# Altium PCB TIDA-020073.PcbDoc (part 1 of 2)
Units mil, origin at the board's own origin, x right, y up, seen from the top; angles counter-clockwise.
Board outline 2125.98 x 2598.43 mil, 4 copper layers (Top Copper, Signal Layer 1, Signal Layer 2, Bottom Copper), stack 62.45 mil thick; 144 components, 83 nets, 376 pads, 155 vias.
Unrouted connection lines stored in the file: 1.
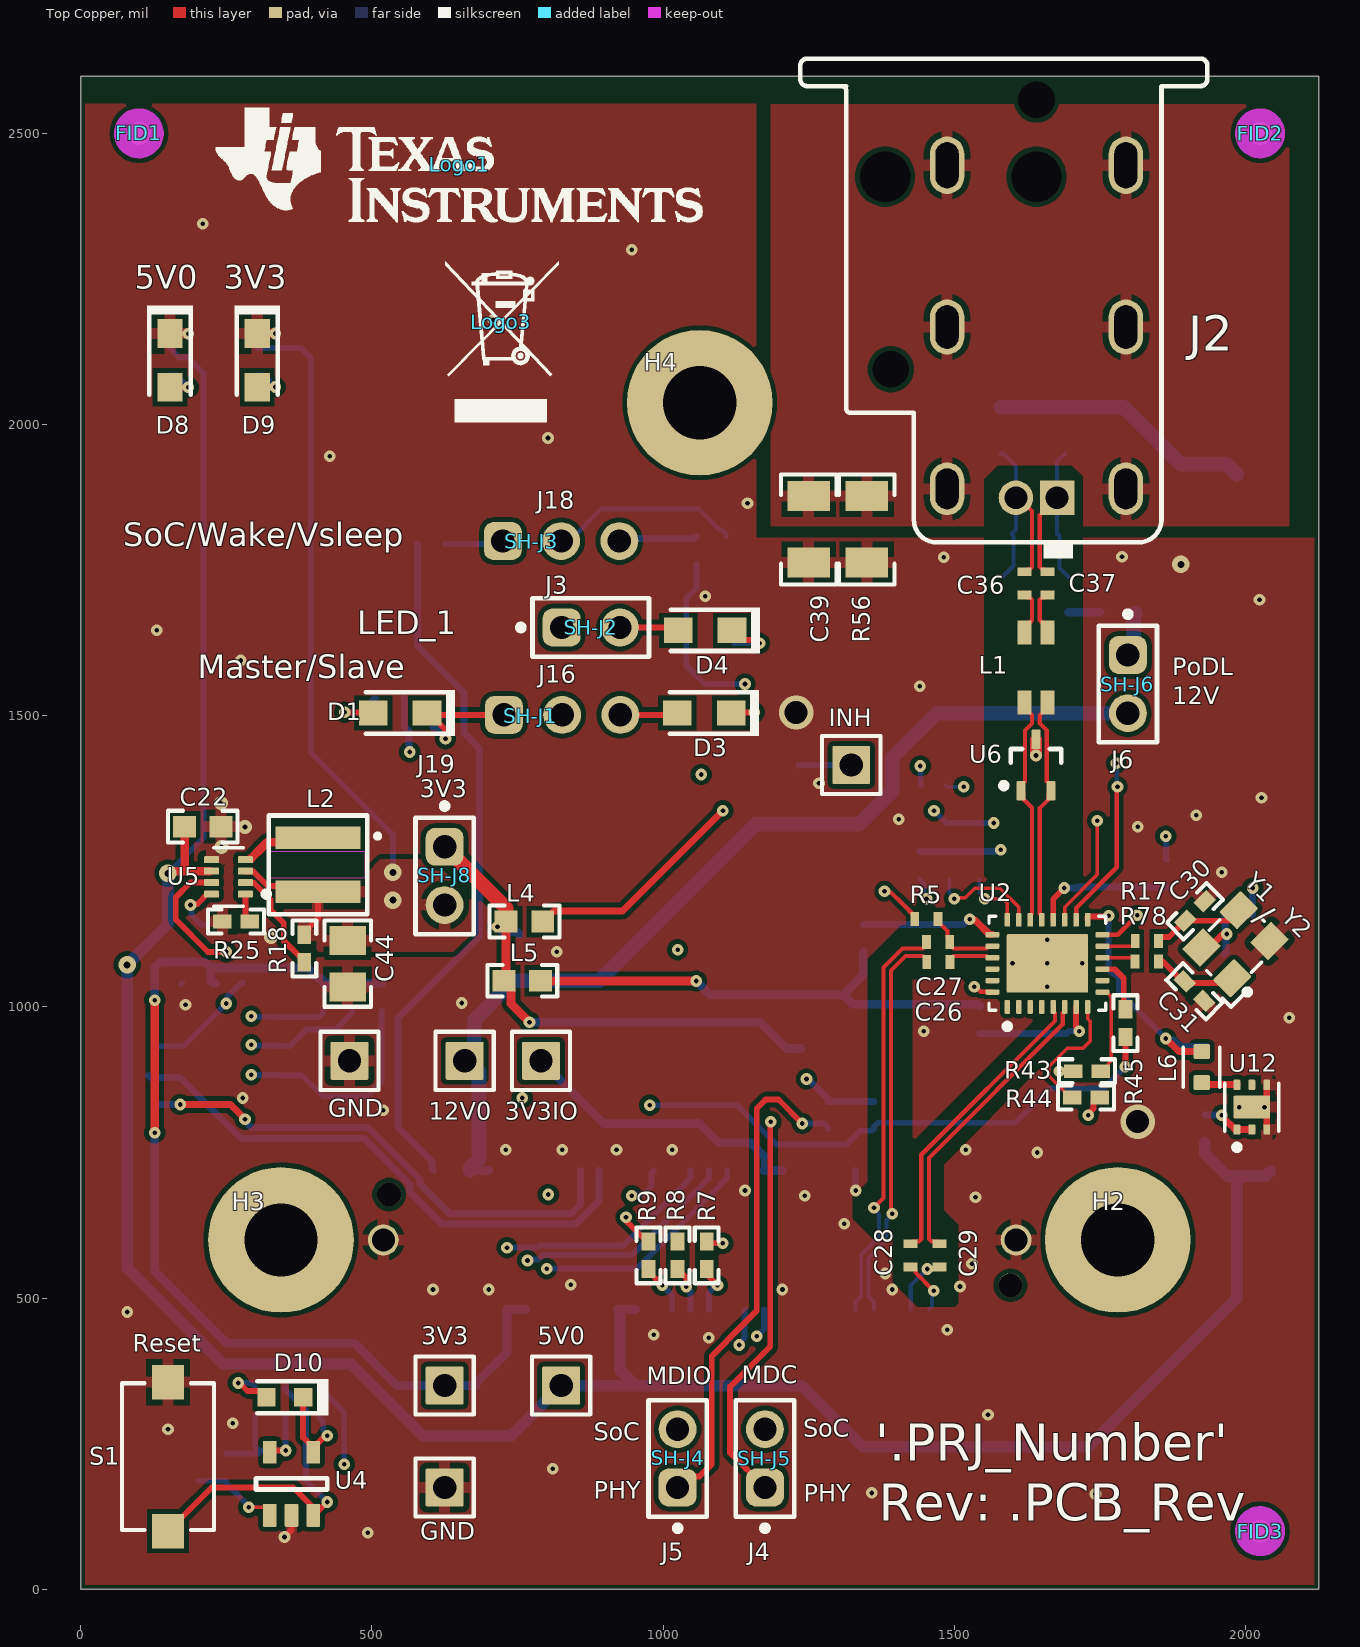
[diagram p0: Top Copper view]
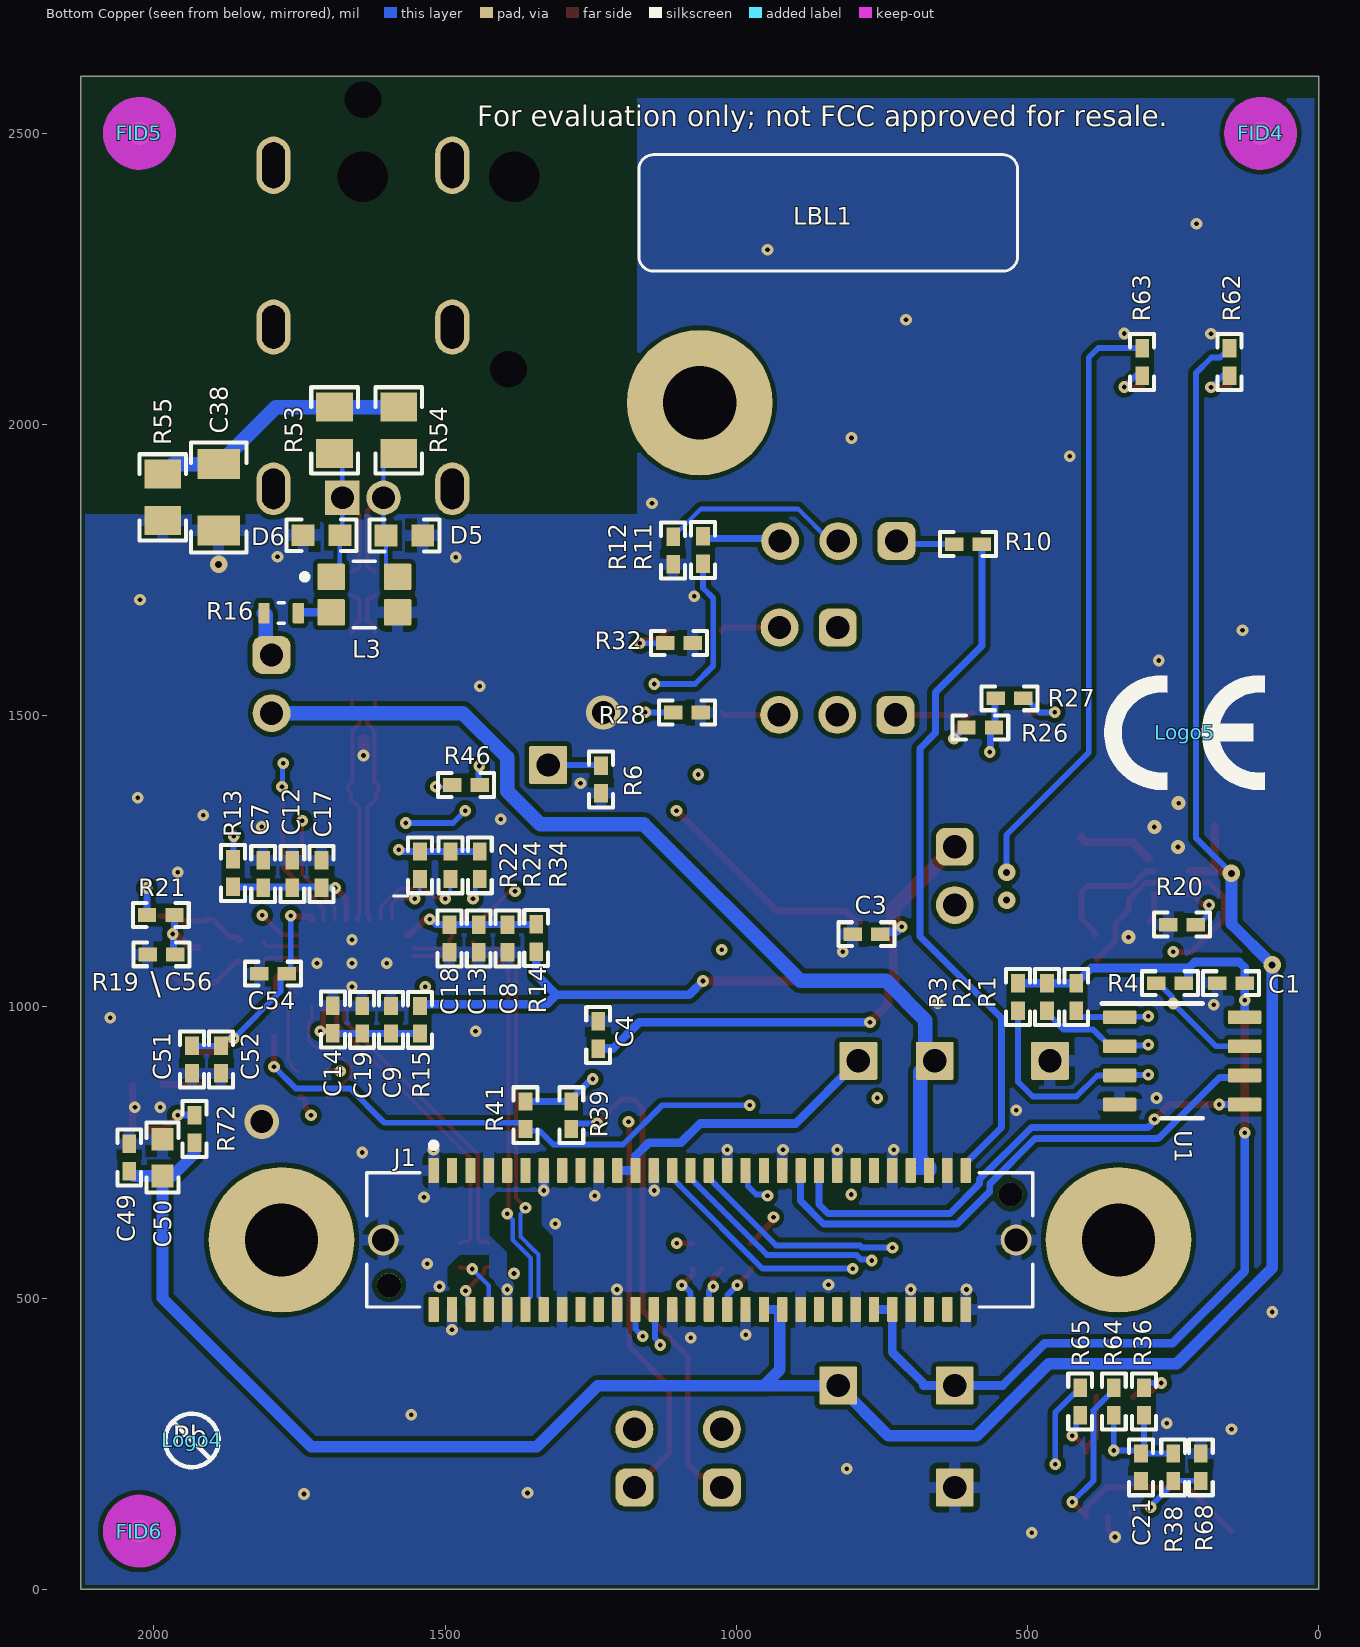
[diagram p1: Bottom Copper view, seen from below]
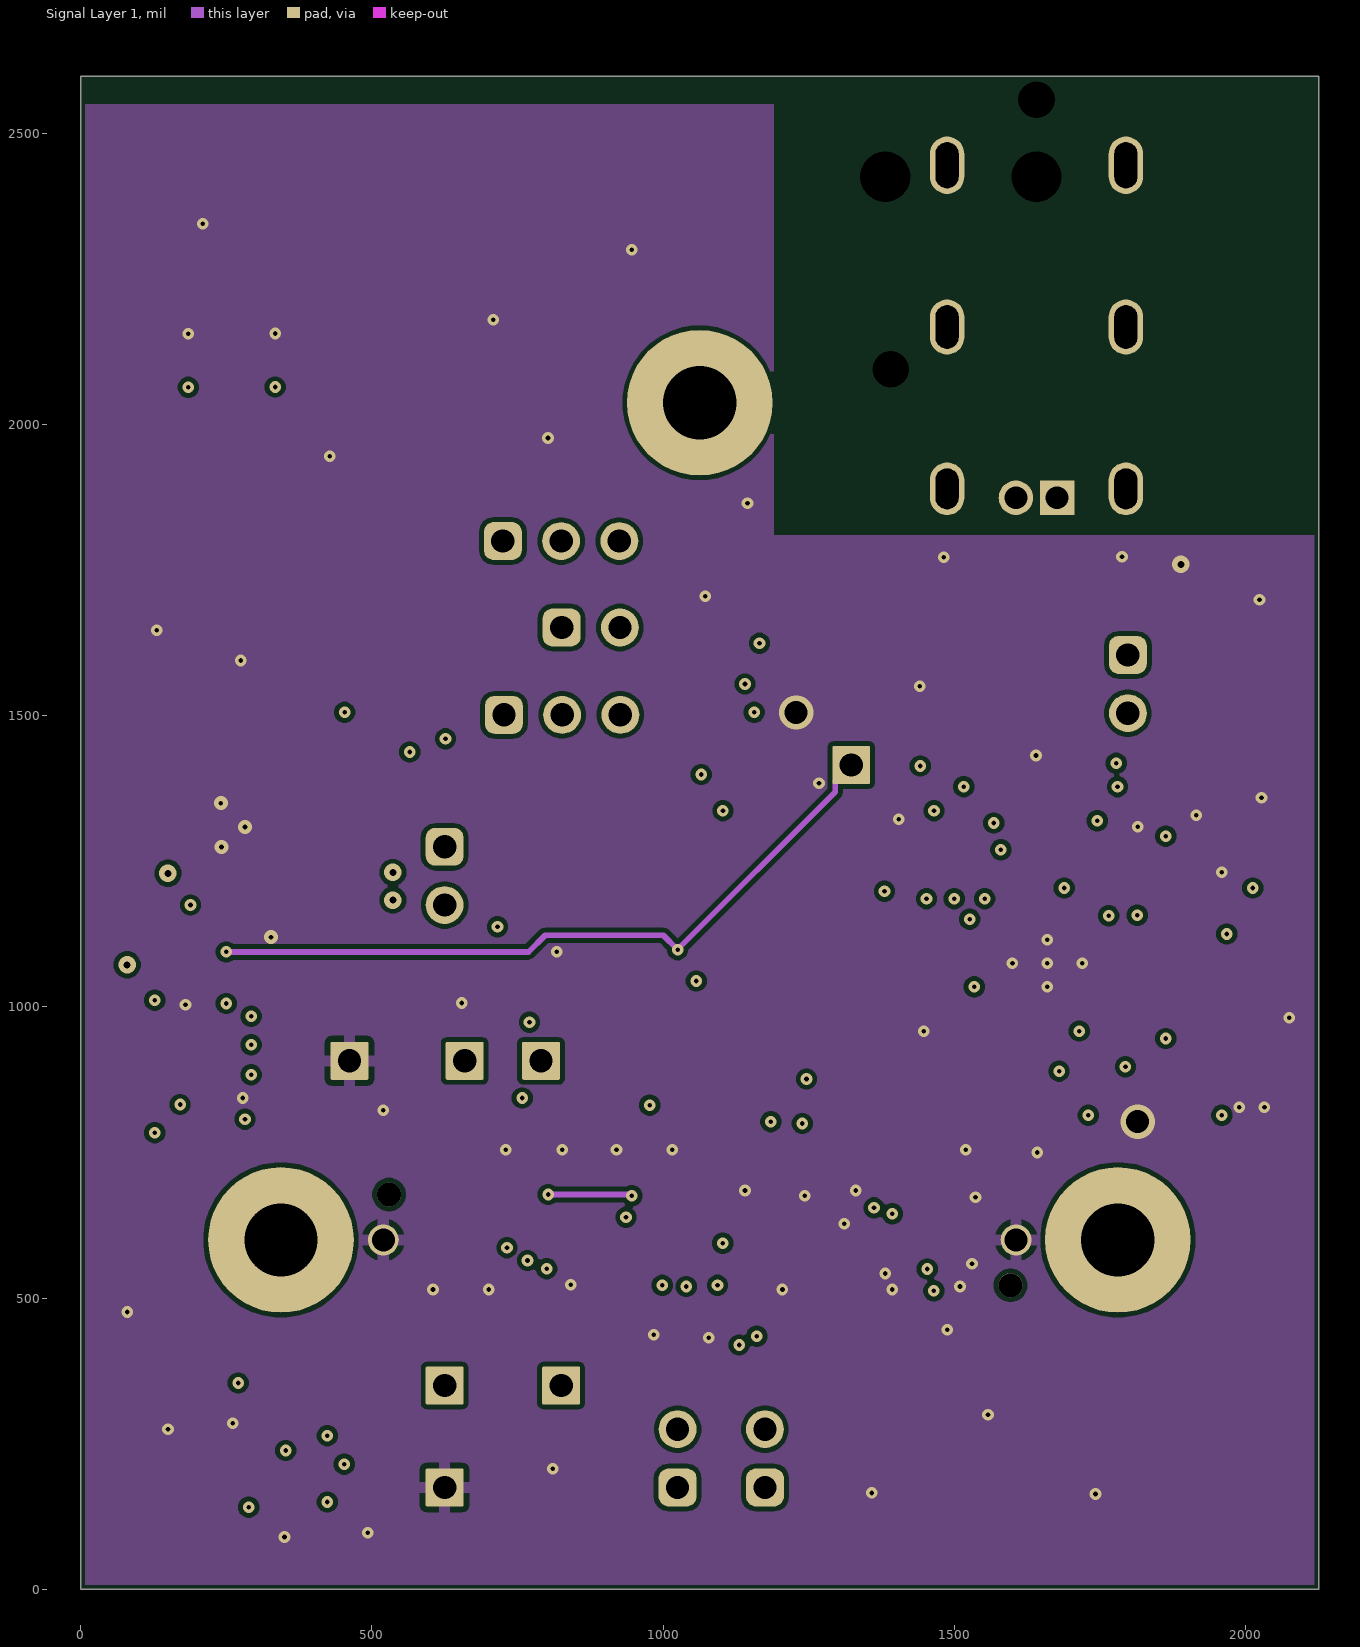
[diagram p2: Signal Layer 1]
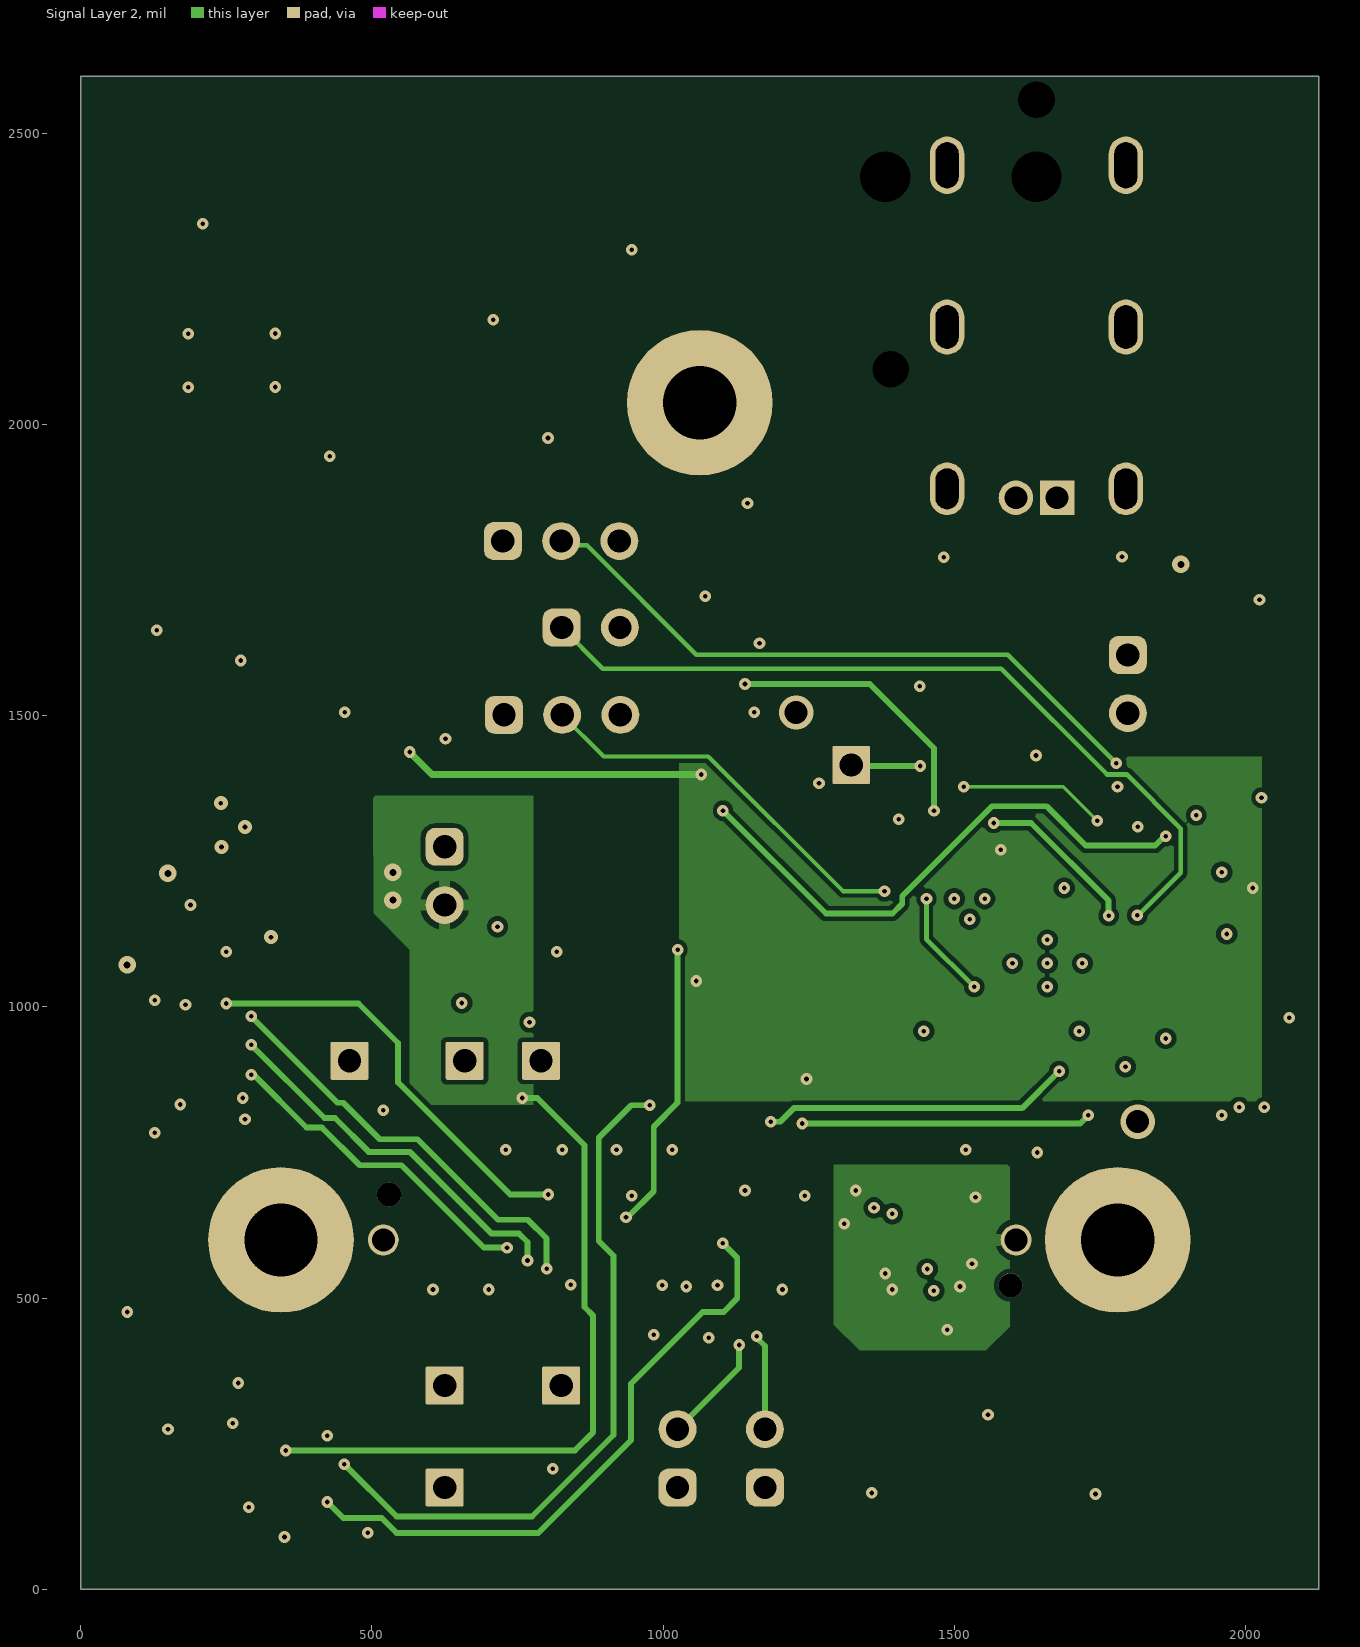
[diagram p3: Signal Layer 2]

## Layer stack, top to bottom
Top Mask: solder mask 0.591, Solder Resist, Dk 3.8
Top Copper: signal copper 1.38
Dielectric 1: prepreg 8.28, 7628, Dk 4.6
Signal Layer 1: signal copper 0.6
Core: core 41.93, FR-4, Dk 4.5
Signal Layer 2: signal copper 0.6
Dielectric 2: prepreg 8.28, 7628, Dk 4.6
Bottom Copper: signal copper 1.38
Bottom Mask: solder mask 0.591, Solder Resist, Dk 3.8

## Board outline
0,0 2125.98,0 2125.98,2598.43 0,2598.43

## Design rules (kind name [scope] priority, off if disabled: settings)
BoardOutlineClearance [All] p1: gap=7.87 ignorepadtopadclearanceinfootprint=FALSE except(15.75: Arc-SplitBarrior Arc-SplitContinuation Track-SplitBarrior Track-SplitContinuation SMDPad-SplitBarrior SMDPad-SplitContinuation THPad-SplitBarrior THPad-SplitContinuation Via-SplitBarrior Via-SplitContinuation Fill-SplitBarrior Fill-SplitContinuation Poly-SplitBarrior Poly-SplitContinuation Region-SplitBarrior Region-SplitContinuation Text-SplitBarrior Text-SplitContinuation)
Clearance "Clearance Bottom Layer" [OnLayer('Bottom Layer')] p1: gap=8 ignorepadtopadclearanceinfootprint=TRUE except(10: Arc-Text Track-Text SMDPad-Text THPad-Text Via-Text Fill-Text Poly-Text Region-Text Text-Text)
Clearance "Clearance Top Layer" [OnLayer('Top Layer')] p2: gap=8 ignorepadtopadclearanceinfootprint=TRUE except(10: Arc-Text Track-Text SMDPad-Text THPad-Text Via-Text Fill-Text Poly-Text Region-Text Text-Text)
Clearance [All] p3: gap=7.87 ignorepadtopadclearanceinfootprint=FALSE except(3.5: Arc-Arc Arc-Track Arc-SMDPad Track-Track Track-SMDPad SMDPad-SMDPad; 5: Arc-Via Track-Via SMDPad-Via THPad-Via Via-Via; 10: Arc-Text Track-Text SMDPad-Text THPad-Text Via-Text Fill-Text Poly-Text Region-Text Text-Text)
DiffPairsRouting [All] p1: maxlimit=6 minlimit=6 mostfreqgap=6 toplayer_minwidth=7.15 toplayer_maxwidth=7.15 toplayer_prefwidth=7.15 midlayer1_minwidth=4.96 midlayer1_maxwidth=4.96 midlayer1_prefwidth=4.96 midlayer2_minwidth=4.95 midlayer2_maxwidth=4.95 midlayer2_prefwidth=4.95 bottomlayer_minwidth=7.15 bottomlayer_maxwidth=7.15 bottomlayer_prefwidth=7.15 impedanceprofiledriven=TRUE impedanceprofileid={56388366-B2A2-40DE-B483-D972356173CC} impedanceprofilevalue=100.000000 maxuncoupledlength=500
HoleSize [All] p1: absolutevalues=TRUE maxlimit=248.03 minlimit=7.87 maxpercent=80.000 minpercent=20.000
MinimumAnnularRing [All] p1: minimumring=3
MinimumSolderMaskSliver [All] p1: minsoldermaskwidth=3.94
PlaneConnect [All] p1: planeconnectstyle=Direct reliefexpansion=20 reliefentries=4 reliefconductorwidth=10 reliefairgap=10
PolygonConnect PolygonConnect_1 [All] p1: thpad.connectstyle=Relief thpad.reliefconductorwidth=20 thpad.reliefentries=4 thpad.polygonreliefangle="90 Angle" thpad.airgapwidth=10 smdpad.connectstyle=Relief smdpad.reliefconductorwidth=20 smdpad.reliefentries=4 smdpad.polygonreliefangle="90 Angle" smdpad.airgapwidth=10 via.connectstyle=Direct via.reliefconductorwidth=20 via.reliefentries=4 via.polygonreliefangle="90 Angle" via.airgapwidth=10
RoutingCorners [All] p1: cornerstyle=Round minsetback=100 maxsetback=100
RoutingVias [All] p1: holewidth=19.68 width=39.37 viastyle="Through Hole" minholewidth=7.87 minwidth=17.72 maxholewidth=39.37 maxwidth=78.74
SilkToBoardRegionClearance [Not ((IsComment or IsDesignator) And (Hide <> 'False')) and not InRegion(1000,500,4000,800)] p1:
SilkToSilkClearance [All] p1: silktosilkclearance=3.94
SilkToSolderMaskClearance [IsPad] p1: minsilkscreentomaskgap=3.94 clearancetoexposedcopper=TRUE
SolderMaskExpansion [All] p1: expansion=4 istentingtop=FALSE
SupplyNets "Schematic Supply Nets_9" [InNet('3V3')] p1: voltage=0.000
SupplyNets "Schematic Supply Nets_8" [InNet('+3V3')] p2: voltage=0.000
SupplyNets "Schematic Supply Nets_7" [InNet('12V0')] p3: voltage=0.000
SupplyNets "Schematic Supply Nets_6" [InNet('+3V3_REG')] p4: voltage=0.000
SupplyNets "Schematic Supply Nets_5" [InNet('GND')] p5: voltage=0.000
SupplyNets "Schematic Supply Nets_4" [InNet('GND_PHY')] p6: voltage=0.000
SupplyNets "Schematic Supply Nets_3" [InNet('Vsleep')] p7: voltage=0.000
SupplyNets "Schematic Supply Nets_2" [InNet('3V3IO')] p8: voltage=0.000
SupplyNets "Schematic Supply Nets_1" [InNet('5V0')] p9: voltage=0.000
SupplyNets "Schematic Supply Nets" [InNet('Vpu33')] p10: voltage=0.000
Width [All] p1: maxlimit=100 minlimit=3.5 preferedwidth=15
22 further rules are at their usual default settings.

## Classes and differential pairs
component class Shunt: SH-J1 SH-J2 SH-J3 SH-J4 SH-J5 SH-J6 SH-J8
component class "Mounting Holes": H2 H3 H4
component class Power_Reset: C21 C22 C44 C49 C50 C51 C52 C54 D8 D9 D10 INH J19 L2 L6 R6 R18 R20 R25 R36 R38 R62 R63 R64 R65 R68 R72 S1 U4 U5 U12
component class Header: 3V3 3V3IO 5V0 12V0 GND INH J3 J4 J5 J6 J16 J18 J19
component class "Connector & Mem": 3V3 3V3IO 5V0 12V0 C1 C28 C29 GND J1 J4 J5 R1 R2 R3 R4 R7 R8 R9 R10 U1
component class Conn-TE: C36 C37 C38 C39 D5 D6 J2 J6 L1 L3 R16 R53 R54 R55 R56 U6
component class "Automotive Ethernet PHY": C3 C4 C7 C8 C9 C12 C13 C14 C17 C18 C19 C26 C27 C30 C31 C56 D1 D3 D4 J3 J16 J18 L4 L5 R5 R11 R12 R13 R14 R15 R17 R19 R21 R22 R24 R26 R27 R28 R32 R34 R39 R41 R43 R44 R45 R46 R78 U2 Y1 Y2
component class Logo: Logo1
component class Hardware: FID1 FID2 FID3 FID4 FID5 FID6 H2 H3 H4 LBL1 Logo1 Logo2 Logo3 Logo4 Logo5 SH-J1 SH-J2 SH-J3 SH-J4 SH-J5 SH-J6 SH-J8 ZZ1 ZZ2 ZZ3 ZZ4
component class FiducialMark: FID1 FID2 FID3 FID4 FID5 FID6
component class AssemblyNote: ZZ1 ZZ2 ZZ3 ZZ4
component class Label: LBL1
differential pair TXC: +TXC_P -TXC_N
differential pair RXP: +RXP_P -RXP_N
differential pair TX: +TX_P -TX_N
differential pair TRD3: +TRD3_P -TRD3_N
differential pair TRD2: +TRD2_P -TRD2_N
differential pair TRD1: +TRD1_P -TRD1_N
differential pair RX: +RX_P -RX_N

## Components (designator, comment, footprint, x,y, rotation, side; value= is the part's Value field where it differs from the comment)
3V3 "TSW-101-07-G-S" TSW-101-07-G-S 625,350 r0 top
3V3IO "TSW-101-07-G-S" TSW-101-07-G-S 790.59,907.52 r90 top
5V0 "TSW-101-07-G-S" TSW-101-07-G-S 825,350 r0 top
12V0 "TSW-101-07-G-S" TSW-101-07-G-S 659.41,907.52 r0 top
C1 "C1005X5R1H104K050BB" 0402 150.98,1040.89 r180 bottom value=0.1uF
C3 "GRM155R61A106ME11" 0402 776.57,1125 r0 bottom value=10uF
C4 "GRM155R61A106ME11" 0402 1237.36,951.96 r90 bottom value=10uF
C7 "C1005X5R1V225K050BC" 0402_065 1812.54,1228.06 r90 bottom value=2.2uF
C8 "C1005X5R1V225K050BC" 0402_065 1393.13,1117.48 r270 bottom value=2.2uF
C9 "C1005X5R1V225K050BC" 0402_065 1592.91,977.96 r90 bottom value=2.2uF
C12 "C1005X5R1H104K050BB" 0402 1762.54,1228.06 r270 bottom value=0.1uF
C13 "C1005X5R1H104K050BB" 0402 1442.49,1117.48 r90 bottom value=0.1uF
C14 "C1005X5R1H104K050BB" 0402 1692.88,978.46 r270 bottom value=0.1uF
C17 "GRM155R61C103KA01D" 0402 1712.54,1228.06 r90 bottom value=0.01uF
C18 "GRM155R61C103KA01D" 0402 1492.44,1117.48 r270 bottom value=0.01uF
C19 "GRM155R61C103KA01D" 0402 1642.6,977.96 r90 bottom value=0.01uF
C21 "C1005X5R1H104K050BB" 0402 305.25,209.65 r270 bottom value=0.1uF
C22 "C1608X5R1E106M080AC" 0603 209.7,1309.58 r0 top value=10uF
C26 "C1005X5R1H104K050BB" 0402S 1472.61,1077.03 r0 top value=0.1uF
C27 "C1005X5R1H104K050BB" 0402S 1472.49,1111.15 r0 top value=0.1uF
C28 "GRM155R61C103KA01D" 0402S 1425,573.62 r90 top value=0.01uF
C29 "GRM155R61C103KA01D" 0402S 1475,573.62 r90 top value=0.01uF
C30 "C0402C270J5GACTU" 0402 1913.35,1164.68 r45 top value=27pF
C31 "C0402C270J5GACTU" 0402 1912.51,1027.13 r315 top value=27pF
C36 "C1005X5R1H104K050BB" 0402S 1620.67,1727.32 r270 top value=0.1uF
C37 "C1005X5R1H104K050BB" 0402S 1660.04,1727.32 r270 top value=0.1uF
C38 "GRM31BR73A472KW01L" 1206 1889.08,1875 r270 bottom value=4700pF
C39 "GRM31BR73A472KW01L" 1206 1250,1820 r270 top value=4700pF
C44 "C2012X5R1A476M125AC" 0805_HV 458.47,1074.35 r270 top value=47uF
C49 "C1005X5R1H104K050BB" 0402 2042.49,741.37 r90 bottom value=0.1uF
C50 "C1608X5R1E106M080AC" 0603 1985.41,741.37 r90 bottom value=10uF
C51 "GRM155R61A106ME11" 0402 1934.81,909.59 r270 bottom value=10uF
C52 "C1005X5R1H104K050BB" 0402 1884.81,909.59 r270 bottom value=0.1uF
C54 "GRM155R61C103KA01D" 0402 1795.5,1057.09 r0 bottom value=0.01uF
C56 "C1005X5R1H104K050BB" 0402 1987.05,1090.4 r180 bottom value=0.1uF
D1 "APT2012LZGCK" APT2012_Green 548.44,1504.84 r0 top value=Green
D3 "APT2012LZGCK" APT2012_Green 1070.68,1504.84 r0 top value=Green
D4 "APT2012LZGCK" APT2012_Green 1072.24,1646.65 r0 top value=Green
D5 "EZAEG3W11AV" 0603 1570.07,1809.37 r180 bottom
D6 "EZAEG3W11AV" 0603 1712.43,1810 r180 bottom
D8 "APT2012LZGCK" APT2012_Green 153.35,2110.04 r90 top value=Green
D9 "APT2012LZGCK" APT2012_Green 303.35,2110.04 r90 top value=Green
D10 "150060RS75000" WL-SMCW_RED 350.62,330.07 r180 top value=Red
FID1 "Fiducial" Fiducial10-20 100,2500 r0 top
FID2 "Fiducial" Fiducial10-20 2025,2500 r0 top
FID3 "Fiducial" Fiducial10-20 2025,100 r0 top
FID4 "Fiducial" Fiducial10-30 100,2500 r180 bottom
FID5 "Fiducial" Fiducial10-30 2025,2500 r180 bottom
FID6 "Fiducial" Fiducial10-30 2025,100 r180 bottom
GND "TSW-101-07-G-S" TSW-101-07-G-S 461.65,907.52 r0 top
GND "TSW-101-07-G-S" TSW-101-07-G-S 625,175 r0 top
H2 "NY PMS 440 0025 PH" "NY PMS 440 0025 PH"#1 1775,600 r0 top
H3 "NY PMS 440 0025 PH" "NY PMS 440 0025 PH"#2 350,600 r0 top locked
H4 "NY PMS 440 0025 PH" "NY PMS 440 0025 PH"#3 1063,2025 r0 top
INH "TSW-101-07-G-S" TSW-101-07-G-S 1323.25,1415.45 r0 top
J1 "1714505106" FP-1714505106_CONN_RCPT60-MFG 1063,600 r180 bottom locked
J2 "9-2304372-1" TE_1PORT_B1-B 1641.24,2557.46 r180 top
J3 "TSW-102-07-G-S" TSW-102-07-G-S 875.95,1651.55 r0 top
J4 "TSW-102-07-G-S" TSW-102-07-G-S 1175,225 r90 top
J5 "TSW-102-07-G-S" TSW-102-07-G-S 1025,225 r90 top
J6 "TSW-102-07-G-S" TSW-102-07-G-S 1798.11,1554.46 r270 top
J16 "TSW-103-07-G-S" TSW-103-07-G-S 826.78,1501.5 r0 top
J18 "TSW-103-07-G-S" TSW-103-07-G-S 825,1800 r0 top
J19 "TSW-102-07-G-S" TSW-102-07-G-S 625,1225 r270 top
L1 "DLW32MH201XK2" FP-DLW32MH201XK2_1210-MFG 1640.35,1582.65 r90 top
L2 "74438356022" WE-MAPI_4020 407.57,1244.15 r270 top
L3 "ADL32VHR-180M" FP-ADL32VHR-180M_SMT_3MM2_2MM5-MFG 1638.84,1708.03 r180 bottom
L4 "BLM18KG601SN1D" 0603 761.96,1146.65 r0 top value="600 ohm"
L5 "BLM18KG601SN1D" 0603 758.38,1044.87 r0 top value="600 ohm"
L6 "BLM18KG102SH1D" FP-BLM18KG102SH1D_0603-MFG 1925,896.85 r90 top
LBL1 "THT-14-423-10" Label_650x200 842.29,2363.35 r180 bottom
Logo1 "Texas Instruments" TI_Stacked_Overlay_Small 650,2445.87 r0 top
Logo2 "FCC disclaimer" FCC_disclaimer 1889.76,-88.58 r0 top
Logo3 "WEEE logo" WEEE_Minimum 721.25,2176.3 r0 top
Logo4 "Pb-Free Symbol" Pb-Free_Overlay_Small 1934.91,255.74 r180 bottom
Logo5 "CE Mark" CE_Mark_5mm 230.5,1471.12 r180 bottom
R1 "RT0402BRD0710KL" 0402 416.49,1017.27 r90 bottom value=10.0k
R2 "RT0402BRD0710KL" 0402 466.49,1017.27 r90 bottom value=10.0k
R3 "RT0402BRD0710KL" 0402 516.49,1017.27 r90 bottom value=10.0k
R4 "RT0402BRD0710KL" 0402 255.5,1040.89 r180 bottom value=10.0k
R5 "CRCW04020000Z0ED" 0402S 1452.26,1151.3 r0 top value=0
R6 "RT0402BRD0710KL" 0402 1232.33,1390.84 r90 bottom value=10.0k
R7 "CRCW04020000Z0ED" 0402 1075,573.62 r270 top value=0
R8 "CRCW04020000Z0ED" 0402 1025,573.62 r270 top value=0
R9 "CRCW04020000Z0ED" 0402 975,573.62 r270 top value=0
R10 "CRCW04020000Z0ED" 0402 602.3,1794.68 r0 bottom value=0
R11 "CRCW04020000Z0ED" 0402 1057.27,1784.42 r270 bottom value=0
R12 "CRCW04022K49FKED" 0402 1108.62,1783.76 r90 bottom value=2.49k
R13 "CRCW04020000Z0ED" 0402 1864.28,1229.77 r90 bottom value=0
R14 "CRCW04020000Z0ED" 0402 1343.78,1118.2 r270 bottom value=0
R15 "CRCW04020000Z0ED" 0402 1543.31,977.96 r90 bottom value=0
R16 "CRCW06030000Z0EAC" FP-CRCW06030000Z0EAC_0603-MFG 1781.59,1676.32 r0 bottom value=0
R17 "CRCW04020000Z0ED" 0402S 1830.91,1113.63 r0 top value=0
R18 "CRCW0402100KFKED" 0402 384.04,1100.35 r90 top value=100k
R19 "CRCW04020000Z0ED" 0402 1987.35,1090.26 r180 bottom value=0
R20 "CRCW040252K3FKED" 0402 234.74,1141.35 r180 bottom value=52.3k
R21 "CRCW04020000Z0ED" 0402 1988.3,1157.96 r0 bottom value=0
R22 "CRCW04024K53FKED" 0402 1543.32,1243.23 r270 bottom value=4.53k
R24 "CRCW04024K53FKED" 0402 1491.05,1243.23 r270 bottom value=4.53k
R25 "CRCW0402249KFKED" 0402 267.04,1146.65 r0 top value=249k
R26 "CRCW04022K49FKED" 0402 581.25,1480 r180 bottom value=2.49k
R27 "CRCW0402470RJNED" 0402 531.25,1530 r180 bottom value=470
R28 "CRCW0402470RJNED" 0402 1085,1505.65 r0 bottom value=470
R32 "CRCW0402470RJNED" 0402 1098.62,1625 r0 bottom value=470
R34 "CRCW04022K49FKED" 0402 1440.53,1243.23 r270 bottom value=2.49k
R36 "CRCW0402470RJNED" 0402 300,322.86 r90 bottom value=470
R38 "ERJ-2RKF1004X" 0402 250,209.65 r270 bottom value=1.00Meg
R39 "CRCW04022K49FKED" 0402 1283.47,814.2 r90 bottom value=2.49k
R41 "CRCW04022K49FKED" 0402 1362.21,814.2 r90 bottom value=2.49k
R43 "CRCW04020000Z0ED" 0402 1728.03,889.8 r180 top value=0
R44 "CRCW04020000Z0ED" 0402 1726.49,844.71 r0 top value=0
R45 "CRCW04020000Z0ED" 0402 1793.98,972.19 r270 top value=0
R46 "CRCW04020000Z0ED" 0402 1464.16,1381.03 r180 bottom value=0
R53 "ERJ-P06F1001V" 0805_HV 1690,1990 r270 bottom value=1.00k
R54 "ERJ-P06F1001V" 0805_HV 1580,1990 r270 bottom value=1.00k
R55 "RT0805BRD07100KL" 0805_HV 1985,1875 r90 bottom value=100k
R56 "CRCW12061M00JNEA" 1206 1350,1820 r270 top value=1.0Meg
R62 "CRCW04022K49FKED" 0402 153.35,2107.68 r90 bottom value=2.49k
R63 "CRCW04022K49FKED" 0402 303.35,2107.68 r90 bottom value=2.49k
R64 "CRCW04022K49FKED" 0402 352,322.86 r270 bottom value=2.49k
R65 "CRCW04020000Z0ED" 0402 409.68,322.86 r90 bottom value=0
R68 "CRCW04020000Z0ED" 0402 202.66,209.65 r270 bottom value=0
R72 "CRCW04020000Z0ED" 0402 1930.41,790.58 r270 bottom value=0
R78 "CRCW0402100RFKED" 0402S 1830.56,1078.28 r0 top value=100
S1 "KSR221GLFS" KSR 150,227.95 r90 top
SH-J1 "SPC02SYAN" SPC02SYAN 772.21,1500.34 r180 top value=1x2
SH-J2 "SPC02SYAN" SPC02SYAN 876.05,1651.76 r180 top value=1x2
SH-J3 "SPC02SYAN" SPC02SYAN 773.32,1800 r180 top value=1x2
SH-J4 "SPC02SYAN" SPC02SYAN 1025,225.99 r90 top value=1x2
SH-J5 "SPC02SYAN" SPC02SYAN 1174.07,225 r90 top value=1x2
SH-J6 "SPC02SYAN" SPC02SYAN 1797.48,1554.46 r90 top value=1x2
SH-J8 "SPC02SYAN" SPC02SYAN 624.58,1226.58 r90 top value=1x2
U1 "CAT24C256WI-GT3" SOIC-8 234.65,907.52 r180 bottom
U2 "DP83TC813" RHF0028A-MFG 1660.04,1074.85 r90 top
U4 "TPS3838K33QDBVRQ1" DBV0005A_N 362.17,181.29 r90 top
U5 "TPS629210QDRLRQ1" DRL0008A-MFG 253.9,1223.41 r180 top
U6 "TPD2E2U06QDCKRQ1" DCK0003A_N 1640.35,1415.45 r90 top
U12 "TPS7B8233DRV-Q1" DRV0006A-MFG 2011,827.98 r90 top
Y1 "ABM8AIG-25.000MHZ-12-2Z-T3" Abracon_ABM8AIG 1982.96,1107.73 r135 top
Y2 "CDC6CE02500CDLE" DLE0004A-MFG 1982.96,1104.38 r135 top
ZZ1 "This Assembly Note is for PCB labels only" AssemblyNoteLabel 5913.35,5325.79 r0 top
ZZ2 "These assemblies are ESD sensitive, ESD precautions shall be observed." AssemblyNote 5913.35,5216.91 r0 top
ZZ3 "These assemblies must be clean and free from flux and all contaminants. Use of no clean flux is not acceptable." AssemblyNote 5913.35,5128.35 r0 top
ZZ4 "These assemblies must comply with workmanship standards IPC-A-610 Class 2, unless otherwise specified." AssemblyNote 5913.35,5039.8 r0 top

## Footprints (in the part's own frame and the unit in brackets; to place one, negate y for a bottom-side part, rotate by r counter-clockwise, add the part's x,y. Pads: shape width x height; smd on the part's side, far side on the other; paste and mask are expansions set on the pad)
0402 [mm] "0402 from SM-752 data"
  rect 0.8x0.6 smd: 1(-0.6,0) 2(0.6,0)
  silkscreen extent -1.22,-0.52 1.22,0.52, body extent -0.55,-0.3 0.55,0.3, height 0.6
0402_065 [mm] "0402"
  rect 0.8x0.6 smd: 1(-0.6,0) 2(0.6,0)
  silkscreen extent -1.22,-0.52 1.22,0.52, body extent -0.55,-0.3 0.55,0.3, height 0.65
0402S [mil] "Based on C0402S footprint from PADS legacy"
  rect 15x24 smd: 1(-20,0) 2(20,0)
  body extent -22,-12 22,12, height 24
0603 [mm] "0603 from SM-752 data"
  rect 1x0.95 smd: 1(-0.8,0) 2(0.8,0)
  silkscreen extent -1.52,-0.69 1.52,0.69, body extent -0.87,-0.47 0.87,0.47, height 1
0805_HV [mil] "0805 with 30mil clearance between pads"
  rect 50x63 smd: 1(-40,0) 2(40,0)
  silkscreen extent -74,-40 74,40, body extent -43,-29 43,29, height 57
1206 [mm] "1206 from SM-752 data"
  rect 1.3x1.85 smd: 1(-1.45,0) 2(1.45,0)
  silkscreen extent -2.4,-1.21 2.4,1.21, body extent -1.7,-0.9 1.7,0.9, height 1.35
Abracon_ABM8AIG [mm] "SMD, 4-Leads, Body 3.2x2.5mm"
  rrect9% 1.1x1.3 smd: 1(-0.95,1.15) 2(-0.95,-1.15) 3(0.95,-1.15) 4(0.95,1.15)
  silkscreen extent -1.8,1.3 -1.28,2.07, body extent -1.3,-1.65 1.3,1.65, height 0.8
APT2012_Green [mm] "SMD, 2-Leads, Body 2x1.25mm"
  rect 1.25x1.1 smd: 1(-1.175,0) 2(1.175,0)
  silkscreen extent -1.5,-1 2.4,1, body extent -1,-0.62 1,0.63, height 0.76
AssemblyNote [mil] "Assembly Note"
AssemblyNoteLabel [mil] "Assembly Note for PCB Labels"
CE_Mark_5mm [mil] "Minimum text height for CE Mark"
  silkscreen extent -138,-98 138,98
DBV0005A_N [mm] "SOT23, 5-Leads, Body 2.9x1.6mm, Pitch 0.95mm, Lead Span 2.8mm, IPC Medium Density"
  rrect17% 1x0.6 smd: 1(-1.375,0.95) 2(-1.375,0) 3(-1.375,-0.95) 4(1.375,-0.95) 5(1.375,0.95)
  silkscreen extent -0.25,-1.55 0.25,1.55, body extent -1.42,-1.46 1.42,1.46, height 1.09
DCK0003A_N [mm] "SOT23, 3-Leads, Body 2.0x1.25mm, Pitch 0.65mm, Lead Span 2.1mm, IPC Medium Density"
  rrect25% 0.85x0.4 smd: 1(-1.125,0.65) 2(-1.125,-0.65) 3(1.125,0)
  silkscreen extent -1.02,-1.1 0.7,1.52, body extent -1.06,-1 1.06,1, height 1.1
DLE0004A-MFG [mm]
  rrect17% 0.6x0.7 smd paste-1000 mask+0: 1(-0.8,1.05) 2(-0.8,-1.05) 3(0.8,-1.05) 4(0.8,1.05)
  silkscreen extent -1.9,-1.65 1.3,1.65, body extent -1.4,-1.75 1.4,1.75, height 0.25
DRL0008A-MFG [mm]
  rrect33% 0.67x0.3 smd paste+0 mask+0: 1(-0.74,0.75) 2(-0.74,0.25) 3(-0.74,-0.25) 4(-0.74,-0.75) 5(0.74,-0.75) 6(0.74,-0.25) 7(0.74,0.25) 8(0.74,0.75)
  silkscreen extent -1.78,-1.28 0.65,1.28, body extent -1.17,-1.35 1.17,1.35, height 0.25
DRV0006A-MFG [mm]
  rrect33% 0.45x0.3 smd paste+0 mask+0: 1(-0.975,0.65) 2(-0.975,0) 3(-0.975,-0.65) 4(0.975,-0.65) 5(0.975,0) 6(0.975,0.65)
  rrect10% 1x1.6 smd paste-1000 mask+0: 7(0,0)
  silkscreen extent -1.87,-1.17 1.05,1.17, body extent -1.3,-1.15 1.3,1.15, height 0.25
FCC_disclaimer [mil]
Fiducial10-20 [mm]
  round 1 smd mask+0.5: 1(0,0)
  Top Copper keep-out circle w1.178: c0,0 r0.5
Fiducial10-30 [mm]
  round 1 smd mask+1: 1(0,0)
  Top Copper keep-out circle w1.678: c0,0 r0.75
FP-1714505106_CONN_RCPT60-MFG [mm]
  rrect22% 0.45x1.1 smd paste+0 mask+0: 1(-11.6,3.03) 2(-10.8,3.03) 3(-10,3.03) 4(-9.2,3.03) 5(-8.4,3.03) 6(-7.6,3.03) 7(-6.8,3.03) 8(-6,3.03) 9(-5.2,3.03) 10(-4.4,3.03) 11(-3.6,3.03) 12(-2.8,3.03) 13(-2,3.03) 14(-1.2,3.03) 15(-0.4,3.03) 16(0.4,3.03) 17(1.2,3.03) 18(2,3.03) 19(2.8,3.03) 20(3.6,3.03) 21(4.4,3.03) 22(5.2,3.03) 23(6,3.03) 24(6.8,3.03) 25(7.6,3.03) 26(8.4,3.03) 27(9.2,3.03) 28(10,3.03) 29(10.8,3.03) 30(11.6,3.03) 31(-11.6,-3.03) 32(-10.8,-3.03) 33(-10,-3.03) 34(-9.2,-3.03) 35(-8.4,-3.03) 36(-7.6,-3.03) 37(-6.8,-3.03) 38(-6,-3.03) 39(-5.2,-3.03) 40(-4.4,-3.03) 41(-3.6,-3.03) 42(-2.8,-3.03) 43(-2,-3.03) 44(-1.2,-3.03) 45(-0.4,-3.03) 46(0.4,-3.03) 47(1.2,-3.03) 48(2,-3.03) 49(2.8,-3.03) 50(3.6,-3.03) 51(4.4,-3.03) 52(5.2,-3.03) 53(6,-3.03) 54(6.8,-3.03) 55(7.6,-3.03) 56(8.4,-3.03) 57(9.2,-3.03) 58(10,-3.03) 59(10.8,-3.03) 60(11.6,-3.03)
  round 1.35 hole 1 paste-2539.97 mask+0: 61(-13.8,0) 62(13.8,0)
  round 1.05 hole 1.05 unplated paste-2539.97 mask+0: ""(-13.55,-1.98) ""(13.55,1.98)
  silkscreen extent -14.53,-2.93 14.53,4.25, body extent -14.4,-3.45 14.4,3.45, height 4.98
FP-ADL32VHR-180M_SMT_3MM2_2MM5-MFG [mm]
  rrect9% 1.2x1.15 smd paste+0 mask+0: 1(-1.45,0.775) 2(-1.45,-0.775) 3(1.45,-0.775) 4(1.45,0.775)
  silkscreen extent -2.73,-1.45 0.48,1.45, body extent -1.95,-1.34 1.95,1.34, height 2.5
FP-BLM18KG102SH1D_0603-MFG [mm]
  rrect15% 0.65x0.7 smd paste+0 mask+0: 1(-0.675,0) 2(0.675,0)
  silkscreen extent -0.88,-0.78 0.87,0.8, body extent -1.1,-0.58 1.1,0.58, height 0.25
FP-CRCW06030000Z0EAC_0603-MFG [mm]
  rrect20% 0.5x0.9 smd paste+0 mask+0: 1(-0.75,0) 2(0.75,0)
  silkscreen extent -0.13,-0.45 0.13,0.45, body extent -0.77,-0.4 0.77,0.4, height 0.5
FP-DLW32MH201XK2_1210-MFG [mm]
  rect 1.05x0.6 smd paste+0 mask+0: 1(-1.525,-0.5) 2(1.525,-0.5) 3(1.525,0.5) 4(-1.525,0.5)
  body extent -2.15,-1.45 2.15,1.45, height 0.25
KSR [mm] "C&K Components SPST switch"
  rect 1.5x1.4 smd: 1(-3.25,0) 2(3.25,0)
  silkscreen extent -3.2,-2 3.2,2, body extent -3,-1.9 3,1.9, height 2.65
Label_650x200 [mil] "Thermal Transfer Label"
  round 1 on Mech14: 0(0,0)
  silkscreen extent -325,-100 325,100, body extent -325,-100 325,100, height 1
"NY PMS 440 0025 PH"#1 [mm] "4-40 nylon screw and mounting hole"
  round 6.35 hole 3.2 paste-2539.97 mask-2539.97: 1(0.152,0)
  body extent -3.3,-3.3 3.3,3.3, height 2.69
"NY PMS 440 0025 PH"#2 [mm] "4-40 nylon screw and mounting hole"
  round 6.35 hole 3.2 mask-2539.97: 1(-0.152,0)
  body extent -3.3,-3.3 3.3,3.3, height 2.69
"NY PMS 440 0025 PH"#3 [mm] "4-40 nylon screw and mounting hole"
  round 6.35 hole 3.2 mask-2539.97: 1(0,0.315)
  body extent -3.3,-3.3 3.3,3.3, height 2.69
Pb-Free_Overlay_Small [mil]
  silkscreen extent -46,-46 46,46
RHF0028A-MFG [mm]
  rrect42% 0.6x0.24 smd paste+0 mask+0: 1(-1.9,1.75) 2(-1.9,1.25) 3(-1.9,0.75) 4(-1.9,0.25) 5(-1.9,-0.25) 6(-1.9,-0.75) 7(-1.9,-1.25) 8(-1.9,-1.75) 15(1.9,-1.75) 16(1.9,-1.25) 17(1.9,-0.75) 18(1.9,-0.25) 19(1.9,0.25) 20(1.9,0.75) 21(1.9,1.25) 22(1.9,1.75)
  rrect42% 0.24x0.6 smd paste+0 mask+0: 9(-1.25,-2.4) 10(-0.75,-2.4) 11(-0.25,-2.4) 12(0.25,-2.4) 13(0.75,-2.4) 14(1.25,-2.4) 23(1.25,2.4) 24(0.75,2.4) 25(0.25,2.4) 26(-0.25,2.4) 27(-0.75,2.4) 28(-1.25,2.4)
  rrect4% 2.55x3.55 smd paste-1000 mask+0: 29(0,0)
  silkscreen extent -2.87,-2.55 2.05,2.55, body extent -2.3,-2.8 2.3,2.8, height 0.25
SOIC-8 [mm] "duplicate of SO-8.  SOIC, 8-Leads, Body 5.0x4.0mm (max), Pitch 1.27mm, IPC Medium Density"
  rrect17% 1.45x0.6 smd: 1(-2.725,1.905) 2(-2.725,0.635) 3(-2.725,-0.635) 4(-2.725,-1.905) 5(2.725,-1.905) 6(2.725,-0.635) 7(2.725,0.635) 8(2.725,1.905)
  silkscreen extent -3.5,-2.5 0.9,2.5, body extent -3,-2.45 3,2.45, height 1.63
SPC02SYAN [mil] "SULLINS"
  round 1 on Mech3: 0(0,0)
  body extent -98,-47 99,47, height 366
TE_1PORT_B1-B [mm] "Header, 1.8mm, 2x1, TH"
  rect 1.5x1.5 hole 1: 1(-0.9,17.35)
  round 1.5 hole 1: 2(0.9,17.35)
  round 0 hole 2.2 unplated: MH1(0,3.35) MH2(6.6,3.35)
  round 0 hole 1.6 unplated: MH3(6.35,11.75) MH4(0,0)
  oval 1.5x2.3 hole 1 slot 1.775 at 90 deg: S1(-3.9,16.963) S4(3.9,16.963)
  oval 1.5x2.4 hole 1 slot 1.89 at 90 deg: S2(-3.9,9.905) S5(3.9,9.905)
  oval 1.5x2.5 hole 1 slot 2 at 90 deg: S3(-3.9,2.85) S6(3.9,2.85)
  silkscreen extent -7.45,-1.8 10.3,20, body extent -7.45,-1.8 10.3,19.3, height 13.5
TI_Stacked_Overlay_Small [mil]
  silkscreen extent -418,-98 418,98
TSW-101-07-G-S [mm] "Samtec 100mil, 1pos, 230 mil above insulator"
  rrect6% 1.65x1.65 hole 1.016: 1(0,0)
  silkscreen extent -1.27,-1.27 1.27,1.27, body extent -1.27,-1.27 1.27,1.27, height 8.38
TSW-102-07-G-S [mm] "Samtec 100mil, 1x2, 230 mil above insulator"
  rrect50% 1.65x1.65 hole 1.016: 1(-1.27,0)
  round 1.65 hole 1.016: 2(1.27,0)
  silkscreen extent -3.17,-1.27 2.54,1.27, body extent -2.54,-1.27 2.54,1.27, height 8.38
TSW-103-07-G-S [mm] "Samtec 100mil, 1x3, 230 mil above insulator"
  rrect50% 1.65x1.65 hole 1.016: 1(-2.54,0)
  round 1.65 hole 1.016: 2(0,0) 3(2.54,0)
  body extent -3.81,-1.27 3.81,1.27, height 8.38
WE-MAPI_4020 [mm] "SMT Shielded Power Inductor, body 4.1x4.1mm"
  rect 0.98x3.7 smd: 1(-1.185,0) 2(1.185,0)
  Top Copper keep-out region: -0.595,2.05 0.595,2.05 0.595,-2.05 -0.595,-2.05
  silkscreen extent -2.15,-2.15 2.15,2.7, body extent -2.05,-2.05 2.05,2.05, height 2.1
WEEE_Minimum [mil] "WEEElie bin"
  silkscreen extent -95,-172 99,104
WL-SMCW_RED [mm] "WURTH"
  rect 0.8x0.8 smd: 1(-0.8,0) 2(0.8,0)
  silkscreen extent -1.9,-0.8 1.2,0.8, body extent -0.85,-0.45 0.85,0.45, height 0.8

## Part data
3V3 3V3IO 5V0 12V0 GND GND INH: library part CMP-0075403-1, "Header, 100mil, 1pos, Gold, TH", Color=Black, Current_A=6.3A, Manufacturer=Samtec, Supplier Part Number 1=SAM1029-01-ND, Voltage_V=550V
C1 C12 C13 C14 C21 C49 C52 C56: library part CMP-0006279-2, "CAP, CERM, 0.1 uF, 50 V, +/- 10%, X5R, 0402", Cap_Case=0402, Manufacturer=TDK, Supplier Part Number 1=445-5942-1-ND, TempCo=X5R, Tolerance_%=10%, Value1="0.039064 ohm", Value2=50V, ValueDisplayed=100nF
C3 C4 C51: library part CMP-0006564-2, "CAP, CERM, 10 uF, 10 V, +/- 20%, X5R, 0402", Cap_Case=0402, Manufacturer=MuRata, TempCo=X5R, Tolerance_%=20%, Value1=Unknown, Value2=10V, ValueDisplayed=10uF
C7 C8 C9: library part CMP-0006283-2, "CAP, CERM, 2.2 uF, 35 V, +/- 10%, X5R, 0402", Cap_Case=0402_065, Manufacturer=TDK, Supplier Part Number 1=445-9028-1-ND, TempCo=X5R, Tolerance_%=10%, Value1="0.005925 ohm", Value2=35V, ValueDisplayed=2.2uF
C17: library part CMP-0006590-2, "CAP, CERM, 0.01 uF, 16 V, +/- 10%, X5R, 0402", Cap_Case=0402, Manufacturer=MuRata, Supplier Part Number 1=GRM155R61C103KA01D-ND, TempCo=X5R, Tolerance_%=10%, Value1=Unknown, Value2=16V, ValueDisplayed=100nF
C18 C19 C28 C29 C54: library part CMP-0006590-2, "CAP, CERM, 0.01 uF, 16 V, +/- 10%, X5R, 0402", Cap_Case=0402, Manufacturer=MuRata, Supplier Part Number 1=GRM155R61C103KA01D-ND, TempCo=X5R, Tolerance_%=10%, Value1=Unknown, Value2=16V, ValueDisplayed=10nF
C22 C50: library part CMP-0007007-5, "CAP, CERM, 10 uF, 25 V, +/- 20%, X5R, 0603", Cap_Case=0603, Manufacturer=TDK, Supplier Part Number 1=445-9015-1-ND, TempCo=X5R, Tolerance_%=20%, Value1="0.004639 ohm", Value2=25V, ValueDisplayed=10uF
C26 C27: library part CMP-0006279-2, "CAP, CERM, 0.1 uF, 50 V, +/- 10%, X5R, 0402", Cap_Case=0402, Manufacturer=TDK, Supplier Part Number 1=445-5942-1-ND, TempCo=X5R, Tolerance_%=10%, Value1="0.039064 ohm", Value2=50V, ValueDisplayed=10nF
C30 C31: library part CMP-0750098-1, "CAP, CERM, 27 pF, 50 V,+/- 5%, C0G/NP0, 0402", Cap_Case=0402, Manufacturer=Kemet, TempCo=C0G/NP0, Tolerance_%=5%, Value2=50V, ValueDisplayed=27pF
C36 C37: library part CMP-0006279-2, "CAP, CERM, 0.1 uF, 50 V, +/- 10%, X5R, 0402", Cap_Case=0402, Manufacturer=TDK, Supplier Part Number 1=445-5942-1-ND, TempCo=X5R, Tolerance_%=10%, Value1="0.039064 ohm", Value2=50V, ValueDisplayed=0.1uF
C38 C39: library part CMP-0008920-2, "CAP, CERM, 4700 pF, 1000 V, +/- 10%, X7R, 1206", Cap_Case=1206, Manufacturer=MuRata, Supplier Part Number 1=490-3498-1-ND, TempCo=X7R, Tolerance_%=10%, Value1=Unknown, Value2=1000V, ValueDisplayed=4n7
C44: library part CMP-0007825-2, "CAP, CERM, 47 uF, 10 V, +/- 20%, X5R, 0805", Cap_Case=0805, Manufacturer=TDK, Supplier Part Number 1=445-8239-1-ND, TempCo=X5R, Tolerance_%=20%, Value1="0.00294 ohm", Value2=10V, ValueDisplayed=47uF
D1 D3 D4 D8 D9: library part CMP-0002953-3, "LED, Green, SMD", Color=Green, Manufacturer=Kingbright, Power_TotalModule=75mW, Value1=0.075W, Value2=2.65V
D5 D6: library part CMP-0086344-1, "Diode, TVS, Bi, AEC-Q101, 0603", Manufacturer=Panasonic
D10: library part CMP-0002947-3, "LED, Red, SMD", Color=Red, Manufacturer="Wurth Elektronik", Power_TotalModule=72mW, Value1=0.072W, Value2=2V
FID1 FID2 FID3 FID4 FID5 FID6: library part CMP-0077181-1, "Fiducial mark.  There is nothing to buy or mount.", Manufacturer=N/A
H2 H3 H4: library part CMP-0003617-1, "Machine Screw, Round, #4-40 x 1/4, Nylon, Philips panhead", Manufacturer="B&F Fastener Supply", Supplier Part Number 1=H542-ND
J1: library part CMP-0122299-1, "Conn Shrouded RCP 60 POS 0.8mm Solder ST SMD Emboss T/R", Current_A=800mA, Digikey Part Number=1714505106-ND, Manufacturer=Molex, Mouser Part Number=538-171450-5106, Operating Temperature Range="-40°C to +105°C", Voltage_V=29.9V
J2: library part CMP-0054903-1, "Header(shrouded), 2x1, R/A, TH", Manufacturer="TE Connectivity"
J3 J4 J5 J6 J19: library part CMP-0075405-3, "Header, 100mil, 2x1, Gold, TH", Color=Black, Current_A=6.3A, Manufacturer=Samtec, Supplier Part Number 1=SAM1029-02-ND, Voltage_V=550V
J16 J18: library part CMP-0075407-2, "Header, 100mil, 3x1, Gold, TH", Color=Black, Current_A=6.3A, Manufacturer=Samtec, Supplier Part Number 1=SAM1029-03-ND, Voltage_V=550V
L1: library part CMP-0087001-1, "200µH @ 100kHz 2 Line Common Mode Choke Surface Mount 70mA DCR 4.8 Ohm", Manufacturer=Murata
L2: library part CMP-0099146-1, "WE-MAPI SMT Power Inductor, size 4020, 2.2uH, 4.7A, 35mOhm", Case/Size Code=4020, DC Resistance=29mOhm, DC Resistance Max=35mOhm, Inductance=2.2uH, Manufacturer="Wurth Elektronik", Operating Temperature Max=125°C, Operating Temperature Min=-40°C, Rated Current=4.7A, Saturation Current=6.2A, Self Resonant Frequency=34MHz
L3: library part CMP-0122302-1, "Differential Mode Choke 18uH 370mA 0.84Ohm 3.2x2.5x2.5mm SMT", Manufacturer=TDK, Operating Temperature Range="-40°C to +150°C", Test Frequency=100kHz, Tolerance_%=20%
L4 L5: library part CMP-0003351-2, "Ferrite Bead, 600 ohm @ 100 MHz, 1.3 A, 0603", Manufacturer=MuRata, Supplier Part Number 1=490-5258-1-ND, Value1="0.15 ohm", Value2=1.3A, ValueDisplayed="600 ohm"
L6: library part CMP-0089381-1, "1 kOhms @ 100MHz 1 Power Line Ferrite Bead 0603 (1608 Metric) 1A 200mOhm", Digikey Part Number=490-17348-1-ND, Impedance At Frequency="1kΩ @ 100MHz", Manufacturer=Murata, Mouser Part Number=81-BLM18KG102SH1D, Operating Temperature Range="-55°C to +125°C", Test Frequency=100MHz, Tolerance_%=25%
LBL1: library part CMP-0003625-1, "Thermal Transfer Printable Labels, 0.650\" W x 0.200\" H - 10,000 per roll", Manufacturer=Brady, Supplier Part Number 1=97C5133
Logo1: library part CMP-0074838-1, "Texas Instrument Corporate Signature"
Logo2: library part CMP-0074847-1, "FCC_disclaimer"
Logo3: library part CMP-0074769-3, Manufacturer="Texas Instruments"
Logo4: library part CMP-0074839-1
Logo5: library part CMP-0074844-1
R1 R2 R3 R4 R6: library part CMP-0065360-1, "RES, 10.0 k, .1%, .0625 W, 0402", Manufacturer="Yageo America", Power_W=62.5mW, Supplier Part Number 1=YAG1346CT-ND, TempCo="25 ppm/C", Tolerance_%=0.1%, Value1=.1%, Value2=.0625W, Value_Code=10k0, ValueDisplayed=10.0k
R5 R7 R8 R9 R10 R11 R13 R14 R15 R17 R19 R21 R43 R44 R45 R46 R65 R68 R72: library part CMP-0026822-3, "RES, 0, 5%, 0.063 W, AEC-Q200 Grade 0, 0402", Manufacturer=Vishay-Dale, Power_W=63mW, Supplier Part Number 1=541-0.0JCT-ND, TempCo="200 ppm/C", Tolerance_%=5%, Value2=0.063W, Value_Code=0000, ValueDisplayed=0
R12 R34 R39 R41 R62 R63 R64: library part CMP-0026237-2, "RES, 2.49 k, 1%, 0.063 W, AEC-Q200 Grade 0, 0402", Manufacturer=Vishay-Dale, Power_W=63mW, Supplier Part Number 1=541-2.49KLCT-ND, TempCo="100 ppm/C", Tolerance_%=1%, Value2=0.063W, Value_Code=2k49, ValueDisplayed=2.49k
R16: library part CMP-0094742-1, "CRCW Series 0603 0.1 W 0 Ohm Jumper Surface Mount Thick Film Chip Resistor", Digikey Part Number=541-4012-1-ND, Manufacturer=Vishay, Mouser Part Number=71-CRCW06030000Z0EAC, Octopart Part Number=1150d8e37ac9ce97, Operating Temperature Range="-55°C to +155°C", Power_W=100mW
R18: library part CMP-0025950-3, "RES, 100 k, 1%, 0.063 W, AEC-Q200 Grade 0, 0402", Manufacturer=Vishay-Dale, Power_W=63mW, Supplier Part Number 1=541-100KLCT-ND, TempCo="100 ppm/C", Tolerance_%=1%, Value2=0.063W, Value_Code=100k
R20: library part CMP-0026441-2, "RES, 52.3 k, 1%, 0.063 W, AEC-Q200 Grade 0, 0402", Manufacturer=Vishay-Dale, Power_W=63mW, Supplier Part Number 1=541-52.3KLCT-ND, TempCo="100 ppm/C", Tolerance_%=1%, Value2=0.063W, Value_Code=52k3, ValueDisplayed=52.3k
R22 R24: library part CMP-0026410-2, "RES, 4.53 k, 1%, 0.063 W, AEC-Q200 Grade 0, 0402", Manufacturer=Vishay-Dale, Power_W=63mW, Supplier Part Number 1=541-4.53KLCT-ND, TempCo="100 ppm/C", Tolerance_%=1%, Value2=0.063W, Value_Code=4k53, ValueDisplayed=4.53k
R25: library part CMP-0026193-2, "RES, 249 k, 1%, 0.063 W, AEC-Q200 Grade 0, 0402", Manufacturer=Vishay-Dale, Power_W=63mW, Supplier Part Number 1=541-249KLCT-ND, TempCo="100 ppm/C", Tolerance_%=1%, Value2=0.063W, Value_Code=249k
R26: library part CMP-0026237-2, "RES, 2.49 k, 1%, 0.063 W, AEC-Q200 Grade 0, 0402", Manufacturer=Vishay-Dale, Power_W=63mW, Supplier Part Number 1=541-2.49KLCT-ND, TempCo="100 ppm/C", Tolerance_%=1%, Value2=0.063W, Value_Code=2k49
R27 R28 R32 R36: library part CMP-0026934-3, "RES, 470, 5%, 0.063 W, AEC-Q200 Grade 0, 0402", Manufacturer=Vishay-Dale, Power_W=63mW, Supplier Part Number 1=541-470JCT-ND, TempCo="200 ppm/C", Tolerance_%=5%, Value2=0.063W, Value_Code=470R, ValueDisplayed=470
R38: library part CMP-0026660-1, "RES, 1.00 M, 1%, 0.1 W, 0402", Manufacturer=Panasonic, Power_W=100mW, Supplier Part Number 1=P1.00MLCT-ND, TempCo="100 ppm/C", Tolerance_%=1%, Value2=0.1W, Value_Code=1M00, ValueDisplayed=1M
R53 R54: library part CMP-0021848-2, "RES, 1.00 k, 1%, 0.25 W, 0805", Manufacturer=Panasonic, Power_W=250mW, Supplier Part Number 1=P16058CT-ND, TempCo="100 ppm/C", Tolerance_%=1%, Value2=0.25W, Value_Code=1k00, ValueDisplayed=1k0
R55: library part CMP-0019441-2, "RES, 100 k, 0.1%, 0.125 W, 0805", Manufacturer="Yageo America", Power_W=125mW, TempCo="25 ppm/C", Tolerance_%=0.1%, Value2=0.125W, Value_Code=100k
R56: library part CMP-0018610-3, "RES, 1.0 M, 5%, 0.25 W, AEC-Q200 Grade 0, 1206", Manufacturer=Vishay-Dale, Power_W=250mW, Supplier Part Number 1=541-1.0MECT-ND, TempCo="200 ppm/C", Tolerance_%=5%, Value2=0.25W, Value_Code=1M00, ValueDisplayed=1M0
R78: library part CMP-0025951-3, "RES, 100, 1%, 0.063 W, AEC-Q200 Grade 0, 0402", Manufacturer=Vishay-Dale, Power_W=63mW, Supplier Part Number 1=541-100LCT-ND, TempCo="100 ppm/C", Tolerance_%=1%, Value2=0.063W, Value_Code=100R, ValueDisplayed=100
S1: library part CMP-0002170-2, "Switch, Normally open, 2.3N force, 200k operations, SMD", CurrentRating_mA=1.001kA, Manufacturer="C&K Components"
SH-J1 SH-J2 SH-J3 SH-J4 SH-J5 SH-J6 SH-J8: library part CMP-0003642-1, "Shunt, 100mil, Flash Gold, Black", Manufacturer="Sullins Connector Solutions", Supplier Part Number 1=S9001-ND
U1: library part CMP-0005313-2, "256 kb I2C CMOS Serial EEPROM, SOIC-8", Manufacturer="ON Semiconductor", Supplier Part Number 1=CAT24C256WI-GT3OSCT-ND
U2: library part CMP-0090093-1, "TC-10 Compliant 100Base-T1 Automotive Ethernet PHY", Manufacturer="Texas Instruments", Max Supply Voltage=3.63V, Min Supply Voltage=1.62V, Operating Temperature Range="-40°C to +125°C"
U4: library part CMP-0074267-1, "Nanopower Supervisory Circuits for Automotive, DBV0005A (SOT-23-5)", Alternate Manufacturer="Texas Instruments"
U5: library part CMP-0089687-1, "3-V to 17-V, Synchronous Buck Converters in 1.6 mm x 2.1 mm SOT583 Package", Manufacturer="Texas Instruments", Max Supply Voltage=17V, Min Supply Voltage=3V, Nominal Supply Current=8mA, Operating Temperature Range="-40°C to +150°C", Output Voltage=0.4-5.5V, Switching Frequency=2.5MHz
U6: library part CMP-0073595-1, "Automotive Dual-Channel High-Speed ESD Protection Device, DCK0003A (SOT-SC70-3)", Alternate Manufacturer="Texas Instruments"
U12: library part CMP-0090846-1, "300-mA High-Voltage Ultralow-IQ Low-Dropout Regulator", Dropout Voltage=730mV, Manufacturer="Texas Instruments", Max Supply Voltage=40V, Min Supply Voltage=3V, Nominal Supply Current=1.9-2.7uA, Operating Temperature Range="-40°C to +150°C", Output Voltage=3.3V
Y1: library part CMP-0004682-5, "Crystal, 25 MHz, 12pF, AEC-Q200 Grade 1, SMD", Frequency_Fixed=25MHz, Frequency Stability="50 ppm", Load Capacitance="12 pF", Manufacturer="Abracon Corporation"
Y2: library part CMP-0001498-1, "Low Jitter, Low Power, LVCMOS Output, BAW Oscillator", Frequency Stability=20ppm, Frequency_Fixed=25MHz, Manufacturer="Texas Instruments", Max Supply Current=5mA, Max Supply Voltage=3.63V, Min Supply Voltage=1.62V, Operating Temperature Range="-40°C to +125°C"
ZZ1: library part CMP-0003616-3
ZZ2: library part CMP-0077236-1
ZZ3: library part CMP-0077237-1
ZZ4: library part CMP-0077238-1

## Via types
v1: diameter 20, hole 8, Top Copper to Bottom Copper, tented both sides, 137 vias
v2: diameter 19.68, hole 7.87, Top Copper to Bottom Copper, 7 vias
v3: diameter 30, hole 12, Top Copper to Bottom Copper, tented both sides, 5 vias
v4: diameter 24, hole 8, Top Copper to Bottom Copper, tented both sides, 4 vias
v5: diameter 59.06, hole 39.37, Top Copper to Bottom Copper, tented both sides, 2 vias

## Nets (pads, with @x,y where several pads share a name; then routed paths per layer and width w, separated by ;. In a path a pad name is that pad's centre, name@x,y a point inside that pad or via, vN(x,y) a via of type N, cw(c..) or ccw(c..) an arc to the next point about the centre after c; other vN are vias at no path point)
3V3: 3V3.1 C1.2 J1.55 J1.56 R1.2 R2.2 R3.2 R4.2 U1.8 | length 1812.1
  Top Copper w15: v1(127.36,784.2) v1(127.36,1011.71)
  Bottom Copper w15: v1(127.36,784.2) 127.36,546.21 251.17,422.4 470.58,422.4 542.98,350 3V3.1@625,350 675,350 ; U1.8@127.37,982.52 v1(127.36,1011.71) C1.2@127.36,1040.89 127.36,1067.68 137.02,1077.34 213.19,1077.34 223.63,1066.9 ; R4.2@231.88,1040.89 227.94,1040.89 223.63,1045.2 223.63,1066.9 ; R3.2@516.49,1040.89 R2.2@466.49,1040.89 R1.2@416.49,1040.89 416.49,1044.83 412.18,1049.14 408.24,1049.14 390.48,1066.9 223.63,1066.9 ; 679.34,350 675,350 ; J1.55@763.79,480.71 J1.56@732.29,480.71 732.29,407.29 675,350
3V3IO: 3V3IO.1 J1.11 J1.12 | length 506.7
  Bottom Copper w10: J1.12@1173.24,719.29 1173.24,744.27
  Bottom Copper w15: 3V3IO.1@790.59,907.52 898.11,800 1062.24,800 1095.29,766.96 1150.55,766.96 1173.24,744.27 ; J1.12@1173.24,719.29 J1.11@1204.73,719.29
5V0: 5V0.1 C22.1 C49.1 C50.1 J1.49 J1.50 R62.2 R72.2 U5.6 | length 4560.8
  Top Copper w15: v3(150,1229.56) 152.71,1229.56 156.4,1233.26 178.64,1233.26 ; C22.1@178.2,1309.58 178.64,1309.14 178.64,1233.26 ; U5.6@221.58,1233.26 178.64,1233.26
  Bottom Copper w10: v3(150,1229.56) 211.11,1290.68 211.11,2088.29 184.41,2115 169.65,2115 R62.2@153.35,2131.3
  Bottom Copper w15: J1.50@925.62,476.35 J1.50@921.27,480.71 J1.49@952.76,480.71
  Bottom Copper w20: v3(150,1229.56) 150,1142.48 v3(80,1072.48) 80,775.19 80,551.82 244.11,387.7 463.38,387.7 587.11,263.97 738.97,263.97 5V0.1@825,350 825.26,349.74 944.05,349.74 ; J1.50@925.62,476.35 925.62,377.32 948.62,354.32 944.05,349.74 ; R72.2@1930.41,766.96 1930.41,748.22 1968.75,709.87 C50.1@1985.41,709.87 ; C49.1@2042.49,717.74 2034.62,709.87 C50.1@1985.41,709.87 ; 944.05,349.74 1238.02,349.74 1342.81,244.95 1730.19,244.95 1985.41,500.17 C50.1@1985.41,709.87
12V0: 12V0.1 J1.27 J1.28 J6.2 | length 1658.6
  Bottom Copper w15: J1.28@669.3,719.29 J1.27@700.8,719.29
  Bottom Copper w25: 12V0.1@659.41,907.52 675.84,923.95 675.84,977.5 743.03,1044.7 890.44,1044.7 1159.46,1313.72 1336.78,1313.72 1393.71,1370.65 1393.71,1428.31 1469.85,1504.46 J6.2@1798.11,1504.46 ; J1.28@669.3,719.29 669.3,724.8 684.04,739.55 684.04,888.41 12V0.1@683.52,888.93
+3V3: C3.1 C4.1 J19.1 L4.1 L5.1 | length 903.9
  Top Copper w10: L5.1@723.82,1047.94 L5.1@726.89,1044.87
  Top Copper w15: v1(715.9,1137.8) 724.76,1146.65 L4.1@730.47,1146.65 L5.1@730.47,1051.65 ; L5.1@726.89,1044.87 727.87,1044.87 739.07,1033.66 739.07,1005.41 v1(770.74,973.75)
  Top Copper w25: J19.1@625,1275 730.51,1169.49 L4.1@730.51,1150
  Bottom Copper w15: v1(715.9,1137.8) 717.25,1137.8 725.74,1129.31 748.64,1129.31 C3.1@752.95,1125 ; v1(770.74,973.75) 1166.82,973.75 1211.84,928.73 1236.97,928.73 C4.1@1237.36,928.34
+3V3_REG: C21.1 C44.1 J19.2 L2.2 R18.2 R36.1 R38.1 R63.2 R64.2 U4.5 U5.3 | length 2688.5
  Top Copper w10: U5.3@283.04,1233.26 283.94,1232.35 297.03,1232.35 321.53,1207.85 397.21,1207.85 L2.2@407.57,1197.5 407.57,1151.43 384.04,1127.91 R18.2@384.04,1123.97 ; U4.5@330.32,238.58 v1(352,238.58)
  Signal Layer 2 w10: v1(352,238.58) 848.58,238.58 880,270 880,470 865,485 865,762.65 784,843.65 v1(758.38,843.65)
  Bottom Copper w10: R38.1@250,233.27 305.12,233.27 C21.1@305.25,233.4 ; R36.1@300,299.24 300,245.39 C21.1@306.81,238.58 ; R63.2@303.35,2131.3 378.7,2131.3 395,2115 395,1436.93 536.22,1295.71 v3(536.22,1230.99) ; C21.1@308.18,238.58 v1(352,238.58) R64.2@352,299.24
  other v3: 536.22,1183.55
A0: J1.14 R1.1 U1.1 | length 1236.4
  Signal Layer 2 w10: v1(292.72,984.12) 441.21,835.64 451.02,835.64 513.65,773 578.35,773 716.55,634.8 767.86,634.8 800.2,602.47 v1(800.2,550.72)
  Bottom Copper w10: v1(292.72,984.12) 293.52,983.32 341.14,983.32 U1.1@341.94,982.52 409.3,982.52 416.49,989.71 R1.1@416.49,993.65 ; v1(800.2,550.72) 955.1,550.72 1098.61,694.22 1098.61,694.86 1110.24,706.5 J1.14@1110.24,719.29
A1: J1.15 R2.1 U1.2 | length 1232.2
  Signal Layer 2 w10: v1(292.72,935.03) 418.57,809.19 436.58,809.19 494.53,751.24 565.32,751.24 705.71,610.85 752.88,610.85 767.37,596.36 v1(767.37,564.75)
  Bottom Copper w10: v1(292.72,935.03) 293.98,933.78 340.68,933.78 U1.2@341.94,932.52 358.67,932.52 387.26,961.12 437.89,961.12 466.49,989.71 R2.1@466.49,993.65 ; v1(767.37,564.75) 769.28,566.66 786.45,566.66 794.18,574.4 947.29,574.4 1067.11,694.22 1067.11,694.86 1078.75,706.5 J1.15@1078.75,719.29
A2: J1.16 R3.1 U1.3 | length 1312.1
  Signal Layer 2 w10: v1(292.72,883.6) 297.42,883.6 387.83,793.19 414.18,793.19 479.15,728.22 551.04,728.22 692.51,586.75 v1(732,586.75)
  Bottom Copper w10: v1(292.72,883.6) 293.26,883.06 341.4,883.06 U1.3@341.94,882.52 380.2,882.52 416.49,846.23 491.28,846.23 516.49,871.44 R3.1@516.49,993.65 ; v1(732,586.75) 783.9,586.75 787.56,590.4 931.79,590.4 1035.61,694.22 1035.61,694.86 1047.25,706.5 J1.16@1047.25,719.29
BAW_NC: C31.1 R78.2 Y1.1 Y2.1 | length 142.1
  Top Copper w10: R78.2@1854.19,1078.28 1858.12,1078.28 1892.56,1043.84 C31.1@1895.81,1043.84 1898.59,1041.05 1954.54,1041.05 1966.36,1052.88 Y2.1@1976,1052.88
ENA: R8.1
GND: C1.1 C3.2 C4.2 C7.2 C8.2 C9.2 C12.1 C13.1 C14.1 C17.2 C18.2 C19.2 C21.2 C22.2 C30.2 C31.2 C38.2 C39.2 C44.2 C49.2 C50.2 C51.2 C52.2 C54.2 C56.1 D5.2 D6.1 D8.2 D9.2 GND.1 J1.1 J1.4 J1.7 J1.10 J1.13 J1.17 J1.20 J1.23 J1.26 J1.29 J1.32 J1.35 J1.38 J1.41 J1.44 J1.48 J1.51 J1.54 J1.57 J1.60 J1.61 J1.62 L3.3 R6.1 R12.1 R19.1 R20.1 R25.1 R28.1 R32.1 R55.1 R56.2 R68.1 S1.2 U1.4 U2.29 U4.2 U5.5 U6.3 U12.3 U12.4 U12.7 Y1.2 Y2.2 | length 247.3
  Top Copper w10: D8.2@153.35,2156.3 184.41,2156.3 v1(185,2155.71) ; D9.2@303.35,2156.3 v1(333.93,2156.3) ; v1(350,90) 362.4,102.4 U4.2@362.4,125
  Top Copper w12: U12.3@2036.59,789.59 2036.59,824.04 v2(2032.65,827.98) 2036.59,831.92 U12.4@2036.59,866.37
  Top Copper w20: v1(1640.35,1431.65) U6.3@1640.35,1458.82
  Bottom Copper w10: C1.1@172.34,1038.63 C1.1@174.6,1040.89
  Bottom Copper w12: v1(1330.72,685) J1.7@1330.72,719.29
  other v1: 493.08,97 1742.52,163.9 1358.63,165.63 810.81,207.34 150,275.05 260.94,285.01 1558.03,299.86 1078.54,432.25 983.98,437.47 1488.3,445.74 80,476.35 605,515 700.8,515 1205,515 1393.71,515 1509.8,520 841.75,522.87 1381.79,542.49 1530.56,559.35 1311.12,627.67 1536.41,673.35 1243.14,675.98 1140.8,685 1642.6,750.25 730,755 826.78,755 920,755 1015.76,755 1520,755 519.69,822.72 278.59,843.65 1447.83,958.59 2075,981.71 180.13,1003.98 654.29,1006.72 817.57,1094.53 1959.38,1231.29 1815,1309.21 1404.55,1322.58 1915.3,1329.12 2027.61,1359.44 1267.72,1383.97 1440.53,1550.9 275,1595 130.91,1646.65 2024.02,1699.21 1072.24,1705 1481.89,1772.24 1787.99,1773.23 1145,1865 427.84,1945.87 802.48,1977.04 708.76,2180 946.54,2300 210,2345
  other v2: 1989.34,827.98 1660.04,1034.5 1600,1074.85 1660.04,1074.85 1720.08,1074.85 1660.04,1115.21
  other v3: 1889.08,1760
  other v4: 326.86,1119.92 241.89,1274.74 282.28,1309.14 240.67,1350
  other v5: 1815,803.06 1228.48,1505.65
GND_PHY: C39.1 J2.S1 J2.S2 J2.S3 J2.S4 J2.S5 J2.S6 R56.1
INH: INH.1 R6.2 R9.1 R46.2 U5.7 | length 2259.7
  Top Copper w10: U5.7@224.77,1213.57 188.67,1213.57 163.35,1188.25 163.35,1150 218.82,1094.53 v1(250,1094.53) ; v1(936.34,638.8) 938.26,636.89 938.26,631.04 R9.1@975,594.29
  Signal Layer 1 w10: v1(250,1094.53) 769.12,1094.53 797.65,1123.06 1000.44,1123.06 v1(1025,1098.5) 1295.77,1369.27 1295.77,1387.97 INH.1@1323.25,1415.45
  Signal Layer 2 w10: v1(936.34,638.8) 939.05,638.8 983.98,683.74 983.98,794.55 1025,835.57 v1(1025,1098.5) ; INH.1@1323.25,1415.45 1324.92,1413.78 v1(1441.64,1413.78)
  Bottom Copper w10: R6.2@1232.33,1414.46 1233.32,1415.45 INH.1@1323.25,1415.45 ; v1(1441.64,1413.78) 1442.56,1412.86 1442.56,1381.96 R46.2@1443.49,1381.03
LED_1: J3.1 U2.14 | length 1459.9
  Top Copper w8: U2.14@1754.53,1124.06 1780.79,1124.06 v1(1814.23,1157.51)
  Signal Layer 2 w8: J3.1@825.95,1651.55 896.54,1580.96 1580.59,1580.96 1762.33,1399.23 1796.14,1399.23 1889.08,1306.29 1889.08,1230.82 v1@1815,1156.74
MDC: J4.1 R43.2 | length 1236.9
  Top Copper w10: J4.1@1175,175 1115.24,234.76 1115.24,348.1 1184,416.85 1184,801.86 v1(1185.21,803.06) ; v1(1680.03,889.8) R43.2@1704.41,889.8
  Signal Layer 2 w10: v1(1185.21,803.06) 1201.39,803.06 1224.65,826.32 1616.55,826.32 v1(1680.03,889.8)
MDIO: J5.1 R39.1 R44.2 | length 1407.1
  Top Copper w10: J5.1@1025,175 1044.06,194.06 1062.6,194.06 1083.54,215 1083.54,400.24 1109.54,426.24 1109.54,426.93 1161.01,478.4 1161.01,825.78 1176.2,840.97 1198.3,840.97 v1(1239.27,800) ; v1(1730.36,814.2) 1730.36,816.91 1739.36,825.91 1739.36,837.9 1746.17,844.71 R44.2@1750.11,844.71
  Signal Layer 2 w10: v1(1239.27,800) 1716.16,800 v1(1730.36,814.2)
  Bottom Copper w10: v1(1239.27,800) 1276.66,800 1283.47,793.19 R39.1@1283.47,790.58
NetC38_1: C38.1 R53.1 R54.1 R55.2 | length 452.6
  Bottom Copper w25: R54.1@1580,2030 R53.1@1690,2030 1791.17,2030 C38.1@1889.08,1932.09 1967.91,1932.09 R55.2@1985,1915
NetD1_1: D1.1 R27.2 | length 113.7
  Top Copper w10: v1(453.26,1505.8) 501.23,1505.8 D1.1@502.18,1504.84
  Bottom Copper w10: v1(453.26,1505.8) 479.49,1505.8 503.69,1530 R27.2@507.62,1530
